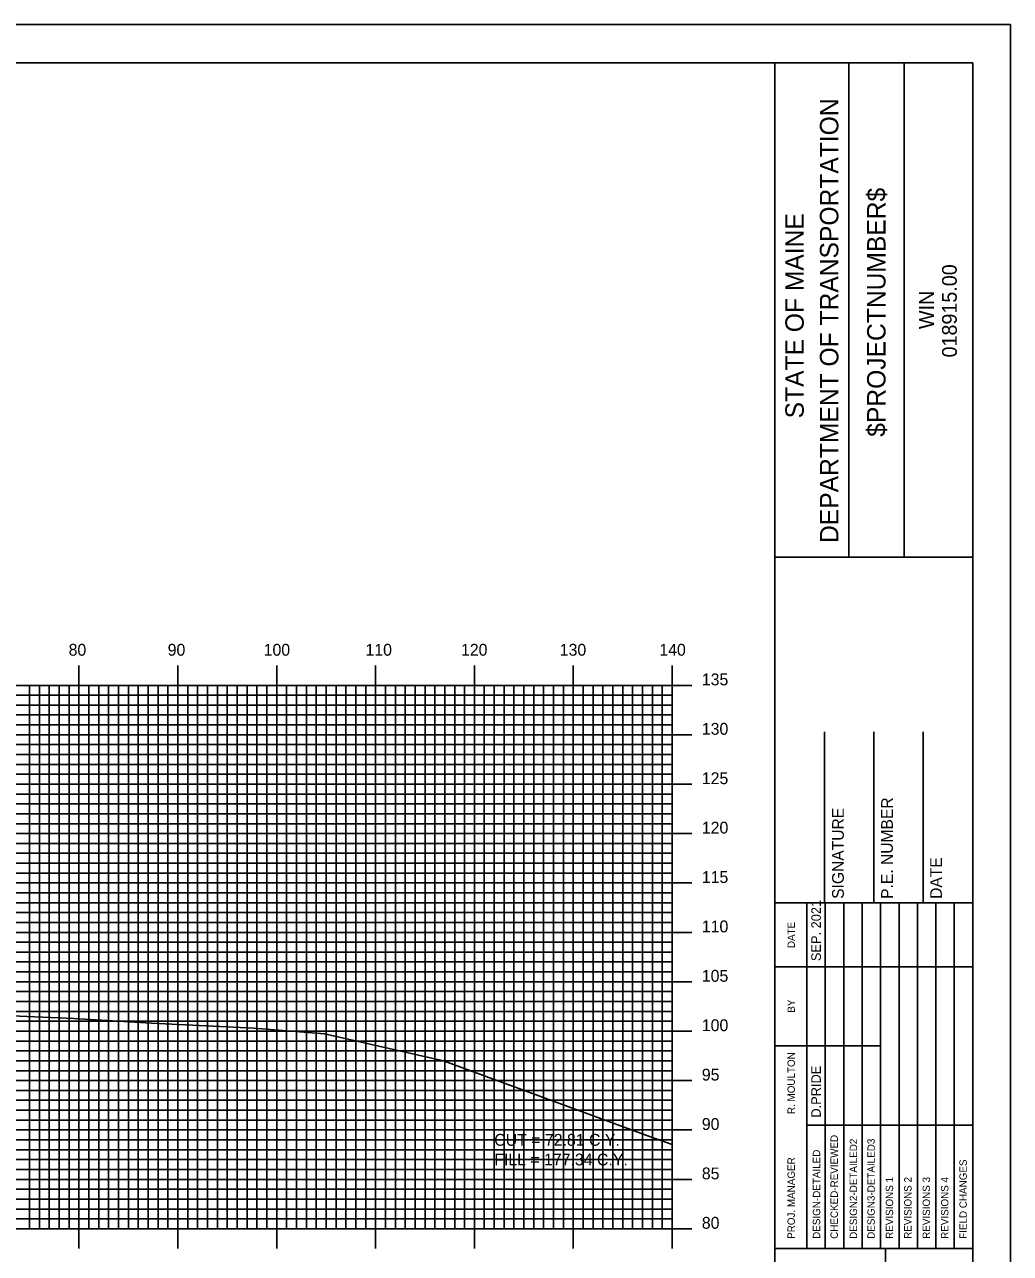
# Model space of a CAD drawing. Extents: x 857658 to 858001, y 364366 to 364586.
# Drawn here: x 857898.3 to 857998.1, y 364461.3 to 364585.7 of the extents above; entities that cross this region are included whole.
import ezdxf

# ---------------------------------------------------------------- set-up
doc = ezdxf.new("R2010")
doc.units = 0
for name, color, linetype in [('BORDER', 7, 'Continuous'), ('D_Text_Standard', 7, 'Continuous'), ('H_V ANNOTATION', 7, 'Continuous'), ('MAJOR', 7, 'Continuous'), ('MINOR', 7, 'Continuous'), ('PLOT BOUNDARY', 7, 'Continuous'), ('S_Roadway_Centerline', 7, 'Continuous')]:
    doc.layers.add(name, color=color, linetype=linetype)

msp = doc.modelspace()

# ---------------------------------------------------------------- linework, layer by layer
at = {"layer": 'BORDER'}
for p, q in [((857974.25, 364371.79), (857974.25, 364581.79)), ((857981.71, 364531.78), (857981.71, 364581.78)), ((857987.3, 364531.78), (857987.3, 364581.78)), ((857974.25, 364531.78), (857994.25, 364531.78)), ((857979.25, 364496.79), (857979.25, 364514.09)), ((857984.25, 364496.79), (857984.25, 364514.09)), ((857989.25, 364496.79), (857989.25, 364514.09)), ((857974.25, 364496.79), (857994.25, 364496.79)), ((857974.25, 364461.79), (857994.25, 364461.79)), ((857985.43, 364391.79), (857985.43, 364461.79))]:
    msp.add_line(p, q, dxfattribs=at)
msp.add_lwpolyline([(857674.25, 364371.79), (857994.25, 364371.79), (857994.25, 364581.79), (857674.25, 364581.79)], close=True, dxfattribs=at)
for points in [[(857977.48, 364490.29), (857977.48, 364496.79)], [(857979.34, 364461.8), (857979.34, 364496.79)], [(857981.21, 364496.79), (857981.21, 364461.8)], [(857983.07, 364461.8), (857983.07, 364496.79)], [(857984.93, 364461.8), (857984.93, 364496.79)], [(857986.8, 364461.8), (857986.8, 364496.79)], [(857988.66, 364461.8), (857988.66, 364496.79)], [(857990.52, 364461.8), (857990.52, 364496.79)], [(857992.39, 364461.8), (857992.39, 364496.79)], [(857977.48, 364461.8), (857977.48, 364495.38)], [(857974.25, 364490.29), (857994.25, 364490.29)], [(857974.25, 364482.29), (857977.48, 364482.29)], [(857977.48, 364482.29), (857984.93, 364482.29)], [(857977.48, 364474.29), (857994.25, 364474.29)]]:
    msp.add_lwpolyline(points, dxfattribs=at)
at = {"layer": 'MAJOR'}
for p, q in [((857903.85, 364520.79), (857903.85, 364518.79)), ((857913.85, 364520.79), (857913.85, 364518.79)), ((857923.85, 364520.79), (857923.85, 364518.79)), ((857933.85, 364520.79), (857933.85, 364518.79)), ((857943.85, 364520.79), (857943.85, 364518.79)), ((857953.85, 364520.79), (857953.85, 364518.79)), ((857963.85, 364520.79), (857963.85, 364518.79)), ((857683.85, 364518.79), (857963.85, 364518.79)), ((857683.85, 364518.79), (857963.85, 364518.79)), ((857903.85, 364463.79), (857903.85, 364518.79)), ((857913.85, 364463.79), (857913.85, 364518.79)), ((857923.85, 364463.79), (857923.85, 364518.79)), ((857933.85, 364463.79), (857933.85, 364518.79)), ((857943.85, 364463.79), (857943.85, 364518.79)), ((857953.85, 364463.79), (857953.85, 364518.79)), ((857965.85, 364518.79), (857961.84, 364518.79)), ((857963.85, 364463.79), (857963.85, 364518.79)), ((857963.85, 364463.79), (857963.85, 364518.79)), ((857683.85, 364513.79), (857963.85, 364513.79)), ((857965.85, 364513.79), (857961.84, 364513.79)), ((857683.85, 364508.79), (857963.85, 364508.79)), ((857965.85, 364508.79), (857961.84, 364508.79)), ((857683.85, 364503.79), (857963.85, 364503.79)), ((857965.85, 364503.79), (857961.84, 364503.79)), ((857683.85, 364498.79), (857963.85, 364498.79)), ((857965.85, 364498.79), (857961.84, 364498.79)), ((857683.85, 364493.79), (857963.85, 364493.79)), ((857965.85, 364493.79), (857961.84, 364493.79)), ((857683.85, 364488.79), (857963.85, 364488.79)), ((857965.85, 364488.79), (857961.84, 364488.79)), ((857683.85, 364483.79), (857963.85, 364483.79)), ((857965.85, 364483.79), (857961.84, 364483.79)), ((857683.85, 364478.79), (857963.85, 364478.79)), ((857965.85, 364478.79), (857961.84, 364478.79)), ((857683.85, 364473.79), (857963.85, 364473.79)), ((857965.85, 364473.79), (857961.84, 364473.79)), ((857683.85, 364468.79), (857963.85, 364468.79)), ((857965.85, 364468.79), (857961.84, 364468.79)), ((857683.85, 364463.79), (857963.85, 364463.79)), ((857683.85, 364463.79), (857963.85, 364463.79)), ((857903.85, 364461.78), (857903.85, 364463.79)), ((857913.85, 364461.78), (857913.85, 364463.79)), ((857923.85, 364461.78), (857923.85, 364463.79)), ((857933.85, 364461.78), (857933.85, 364463.79)), ((857943.85, 364461.78), (857943.85, 364463.79)), ((857953.85, 364461.78), (857953.85, 364463.79)), ((857965.85, 364463.79), (857961.84, 364463.79)), ((857963.85, 364461.78), (857963.85, 364463.79))]:
    msp.add_line(p, q, dxfattribs=at)
at = {"layer": 'MINOR'}
for p, q in [((857683.85, 364517.79), (857963.85, 364517.79)), ((857898.85, 364463.79), (857898.85, 364518.79)), ((857899.85, 364463.79), (857899.85, 364518.79)), ((857900.85, 364463.79), (857900.85, 364518.79)), ((857901.85, 364463.79), (857901.85, 364518.79)), ((857902.85, 364463.79), (857902.85, 364518.79)), ((857904.85, 364463.79), (857904.85, 364518.79)), ((857905.85, 364463.79), (857905.85, 364518.79)), ((857906.85, 364463.79), (857906.85, 364518.79)), ((857907.85, 364463.79), (857907.85, 364518.79)), ((857908.85, 364463.79), (857908.85, 364518.79)), ((857909.85, 364463.79), (857909.85, 364518.79)), ((857910.85, 364463.79), (857910.85, 364518.79)), ((857911.85, 364463.79), (857911.85, 364518.79)), ((857912.85, 364463.79), (857912.85, 364518.79)), ((857914.85, 364463.79), (857914.85, 364518.79)), ((857915.85, 364463.79), (857915.85, 364518.79)), ((857916.85, 364463.79), (857916.85, 364518.79)), ((857917.85, 364463.79), (857917.85, 364518.79)), ((857918.85, 364463.79), (857918.85, 364518.79)), ((857919.85, 364463.79), (857919.85, 364518.79)), ((857920.85, 364463.79), (857920.85, 364518.79)), ((857921.85, 364463.79), (857921.85, 364518.79)), ((857922.85, 364463.79), (857922.85, 364518.79)), ((857924.85, 364463.79), (857924.85, 364518.79)), ((857925.85, 364463.79), (857925.85, 364518.79)), ((857926.85, 364463.79), (857926.85, 364518.79)), ((857927.85, 364463.79), (857927.85, 364518.79)), ((857928.85, 364463.79), (857928.85, 364518.79)), ((857929.85, 364463.79), (857929.85, 364518.79)), ((857930.85, 364463.79), (857930.85, 364518.79)), ((857931.85, 364463.79), (857931.85, 364518.79)), ((857932.85, 364463.79), (857932.85, 364518.79)), ((857934.85, 364463.79), (857934.85, 364518.79)), ((857935.85, 364463.79), (857935.85, 364518.79)), ((857936.85, 364463.79), (857936.85, 364518.79)), ((857937.85, 364463.79), (857937.85, 364518.79)), ((857938.85, 364463.79), (857938.85, 364518.79)), ((857939.85, 364463.79), (857939.85, 364518.79)), ((857940.85, 364463.79), (857940.85, 364518.79)), ((857941.85, 364463.79), (857941.85, 364518.79)), ((857942.85, 364463.79), (857942.85, 364518.79)), ((857944.85, 364463.79), (857944.85, 364518.79)), ((857945.85, 364463.79), (857945.85, 364518.79)), ((857946.85, 364463.79), (857946.85, 364518.79)), ((857947.85, 364463.79), (857947.85, 364518.79)), ((857948.85, 364463.79), (857948.85, 364518.79)), ((857949.85, 364463.79), (857949.85, 364518.79)), ((857950.85, 364463.79), (857950.85, 364518.79)), ((857951.85, 364463.79), (857951.85, 364518.79)), ((857952.85, 364463.79), (857952.85, 364518.79)), ((857954.85, 364463.79), (857954.85, 364518.79)), ((857955.85, 364463.79), (857955.85, 364518.79)), ((857956.85, 364463.79), (857956.85, 364518.79)), ((857957.85, 364463.79), (857957.85, 364518.79)), ((857958.85, 364463.79), (857958.85, 364518.79)), ((857959.85, 364463.79), (857959.85, 364518.79)), ((857960.85, 364463.79), (857960.85, 364518.79)), ((857963.85, 364517.79), (857961.84, 364517.79)), ((857961.85, 364463.79), (857961.85, 364518.79)), ((857962.85, 364463.79), (857962.85, 364518.79)), ((857683.85, 364516.79), (857963.85, 364516.79)), ((857963.85, 364516.79), (857961.84, 364516.79)), ((857683.85, 364515.79), (857963.85, 364515.79)), ((857963.85, 364515.79), (857961.84, 364515.79)), ((857683.85, 364514.79), (857963.85, 364514.79)), ((857963.85, 364514.79), (857961.84, 364514.79)), ((857683.85, 364512.79), (857963.85, 364512.79)), ((857963.85, 364512.79), (857961.84, 364512.79)), ((857683.85, 364511.79), (857963.85, 364511.79)), ((857963.85, 364511.79), (857961.84, 364511.79)), ((857683.85, 364510.79), (857963.85, 364510.79)), ((857963.85, 364510.79), (857961.84, 364510.79)), ((857683.85, 364509.79), (857963.85, 364509.79)), ((857963.85, 364509.79), (857961.84, 364509.79)), ((857683.85, 364507.79), (857963.85, 364507.79)), ((857963.85, 364507.79), (857961.84, 364507.79)), ((857683.85, 364506.79), (857963.85, 364506.79)), ((857963.85, 364506.79), (857961.84, 364506.79)), ((857683.85, 364505.79), (857963.85, 364505.79)), ((857963.85, 364505.79), (857961.84, 364505.79)), ((857683.85, 364504.79), (857963.85, 364504.79)), ((857963.85, 364504.79), (857961.84, 364504.79)), ((857683.85, 364502.79), (857963.85, 364502.79)), ((857963.85, 364502.79), (857961.84, 364502.79)), ((857683.85, 364501.79), (857963.85, 364501.79)), ((857963.85, 364501.79), (857961.84, 364501.79)), ((857683.85, 364500.79), (857963.85, 364500.79)), ((857963.85, 364500.79), (857961.84, 364500.79)), ((857683.85, 364499.79), (857963.85, 364499.79)), ((857963.85, 364499.79), (857961.84, 364499.79)), ((857683.85, 364497.79), (857963.85, 364497.79)), ((857963.85, 364497.79), (857961.84, 364497.79)), ((857683.85, 364496.79), (857963.85, 364496.79)), ((857963.85, 364496.79), (857961.84, 364496.79)), ((857683.85, 364495.79), (857963.85, 364495.79)), ((857963.85, 364495.79), (857961.84, 364495.79)), ((857683.85, 364494.79), (857963.85, 364494.79)), ((857963.85, 364494.79), (857961.84, 364494.79)), ((857683.85, 364492.79), (857963.85, 364492.79)), ((857963.85, 364492.79), (857961.84, 364492.79)), ((857683.85, 364491.79), (857963.85, 364491.79)), ((857963.85, 364491.79), (857961.84, 364491.79)), ((857683.85, 364490.79), (857963.85, 364490.79)), ((857963.85, 364490.79), (857961.84, 364490.79)), ((857683.85, 364489.79), (857963.85, 364489.79)), ((857963.85, 364489.79), (857961.84, 364489.79)), ((857683.85, 364487.79), (857963.85, 364487.79)), ((857963.85, 364487.79), (857961.84, 364487.79)), ((857683.85, 364486.79), (857963.85, 364486.79)), ((857963.85, 364486.79), (857961.84, 364486.79)), ((857683.85, 364485.79), (857963.85, 364485.79)), ((857963.85, 364485.79), (857961.84, 364485.79)), ((857683.85, 364484.79), (857963.85, 364484.79)), ((857963.85, 364484.79), (857961.84, 364484.79)), ((857683.85, 364482.79), (857963.85, 364482.79)), ((857963.85, 364482.79), (857961.84, 364482.79)), ((857683.85, 364481.79), (857963.85, 364481.79)), ((857963.85, 364481.79), (857961.84, 364481.79)), ((857683.85, 364480.79), (857963.85, 364480.79)), ((857963.85, 364480.79), (857961.84, 364480.79)), ((857683.85, 364479.79), (857963.85, 364479.79)), ((857963.85, 364479.79), (857961.84, 364479.79)), ((857683.85, 364477.79), (857963.85, 364477.79)), ((857963.85, 364477.79), (857961.84, 364477.79)), ((857683.85, 364476.79), (857963.85, 364476.79)), ((857963.85, 364476.79), (857961.84, 364476.79)), ((857683.85, 364475.79), (857963.85, 364475.79)), ((857963.85, 364475.79), (857961.84, 364475.79)), ((857683.85, 364474.79), (857963.85, 364474.79)), ((857963.85, 364474.79), (857961.84, 364474.79)), ((857683.85, 364472.79), (857963.85, 364472.79)), ((857683.85, 364471.79), (857963.85, 364471.79)), ((857963.85, 364472.79), (857961.84, 364472.79)), ((857963.85, 364471.79), (857961.84, 364471.79)), ((857683.85, 364470.79), (857963.85, 364470.79)), ((857963.85, 364470.79), (857961.84, 364470.79)), ((857683.85, 364469.79), (857963.85, 364469.79)), ((857963.85, 364469.79), (857961.84, 364469.79)), ((857683.85, 364467.79), (857963.85, 364467.79)), ((857683.85, 364466.79), (857963.85, 364466.79)), ((857963.85, 364467.79), (857961.84, 364467.79)), ((857963.85, 364466.79), (857961.84, 364466.79)), ((857683.85, 364465.79), (857963.85, 364465.79)), ((857963.85, 364465.79), (857961.84, 364465.79)), ((857683.85, 364464.79), (857963.85, 364464.79)), ((857963.85, 364464.79), (857961.84, 364464.79))]:
    msp.add_line(p, q, dxfattribs=at)
at = {"layer": 'PLOT BOUNDARY'}
msp.add_lwpolyline([(857658.06, 364365.67), (857998.06, 364365.67), (857998.06, 364585.67), (857658.06, 364585.67)], close=True, dxfattribs=at)
at = {"layer": 'S_Roadway_Centerline'}
msp.add_lwpolyline([(857893.86, 364485.46), (857903.34, 364485.07), (857911.2, 364484.59), (857921.52, 364484.08), (857928.68, 364483.52), (857940.72, 364480.79), (857961.66, 364473.09), (857963.85, 364472.33)], dxfattribs=at)

# ---------------------------------------------------------------- texts
at = {"layer": 'BORDER'}
for s, height, p in [('DEPARTMENT OF TRANSPORTATION', 1.8635, (857980.66, 364533.2)), ('$PROJECTNUMBER$', 1.8635, (857985.43, 364543.95)), ('STATE OF MAINE', 1.8635, (857977.16, 364545.81)), ('018915.00', 1.491, (857992.64, 364551.98)), ('WIN', 1.491, (857990.32, 364554.85)), ('P.E. NUMBER', 1.1811, (857986.17, 364497.18)), ('SIGNATURE', 1.181, (857981.21, 364497.18)), ('DATE', 1.181, (857991.13, 364497.18)), ('SEP. 2021', 0.969, (857978.89, 364490.88)), ('DATE', 0.743, (857976.26, 364492.2)), ('BY', 0.743, (857976.26, 364485.66)), ('R. MOULTON', 0.745, (857976.26, 364475.4)), ('D.PRIDE', 0.969, (857978.89, 364475.04)), ('CHECKED-REVIEWED', 0.7455, (857980.61, 364462.77)), ('DESIGN2-DETAILED2', 0.7455, (857982.55, 364462.77)), ('DESIGN3-DETAILED3', 0.7455, (857984.34, 364462.77)), ('DESIGN-DETAILED', 0.7455, (857978.82, 364462.77)), ('PROJ. MANAGER', 0.7455, (857976.26, 364462.77)), ('FIELD CHANGES', 0.7455, (857993.65, 364462.77)), ('REVISIONS 1', 0.7455, (857986.2, 364462.77)), ('REVISIONS 2', 0.7455, (857988.06, 364462.77)), ('REVISIONS 3', 0.7455, (857989.93, 364462.77)), ('REVISIONS 4', 0.7455, (857991.79, 364462.77))]:
    msp.add_text(s, height=height, rotation=90, dxfattribs=at).set_placement(p)
at = {"layer": 'D_Text_Standard'}
for s, p in [('CUT = 72.81 C.Y.', (857945.85, 364472.19)), ('FILL = 177.34 C.Y.', (857945.85, 364470.2))]:
    msp.add_text(s, height=1.2, dxfattribs=at).set_placement(p)
at = {"layer": 'H_V ANNOTATION'}
for s, p in [('80', (857902.8, 364521.79)), ('90', (857912.82, 364521.79)), ('100', (857922.53, 364521.79)), ('110', (857932.83, 364521.79)), ('120', (857942.49, 364521.79)), ('130', (857952.48, 364521.79)), ('140', (857962.55, 364521.79)), ('135', (857966.85, 364518.79)), ('130', (857966.85, 364513.79)), ('125', (857966.85, 364508.79)), ('120', (857966.85, 364503.79)), ('115', (857966.85, 364498.79)), ('110', (857966.85, 364493.79)), ('105', (857966.85, 364488.79)), ('100', (857966.85, 364483.79)), ('95', (857966.85, 364478.79)), ('90', (857966.85, 364473.79)), ('85', (857966.85, 364468.79)), ('80', (857966.85, 364463.79))]:
    msp.add_text(s, height=1.2, dxfattribs=at).set_placement(p)

doc.saveas('drawing.dxf')
